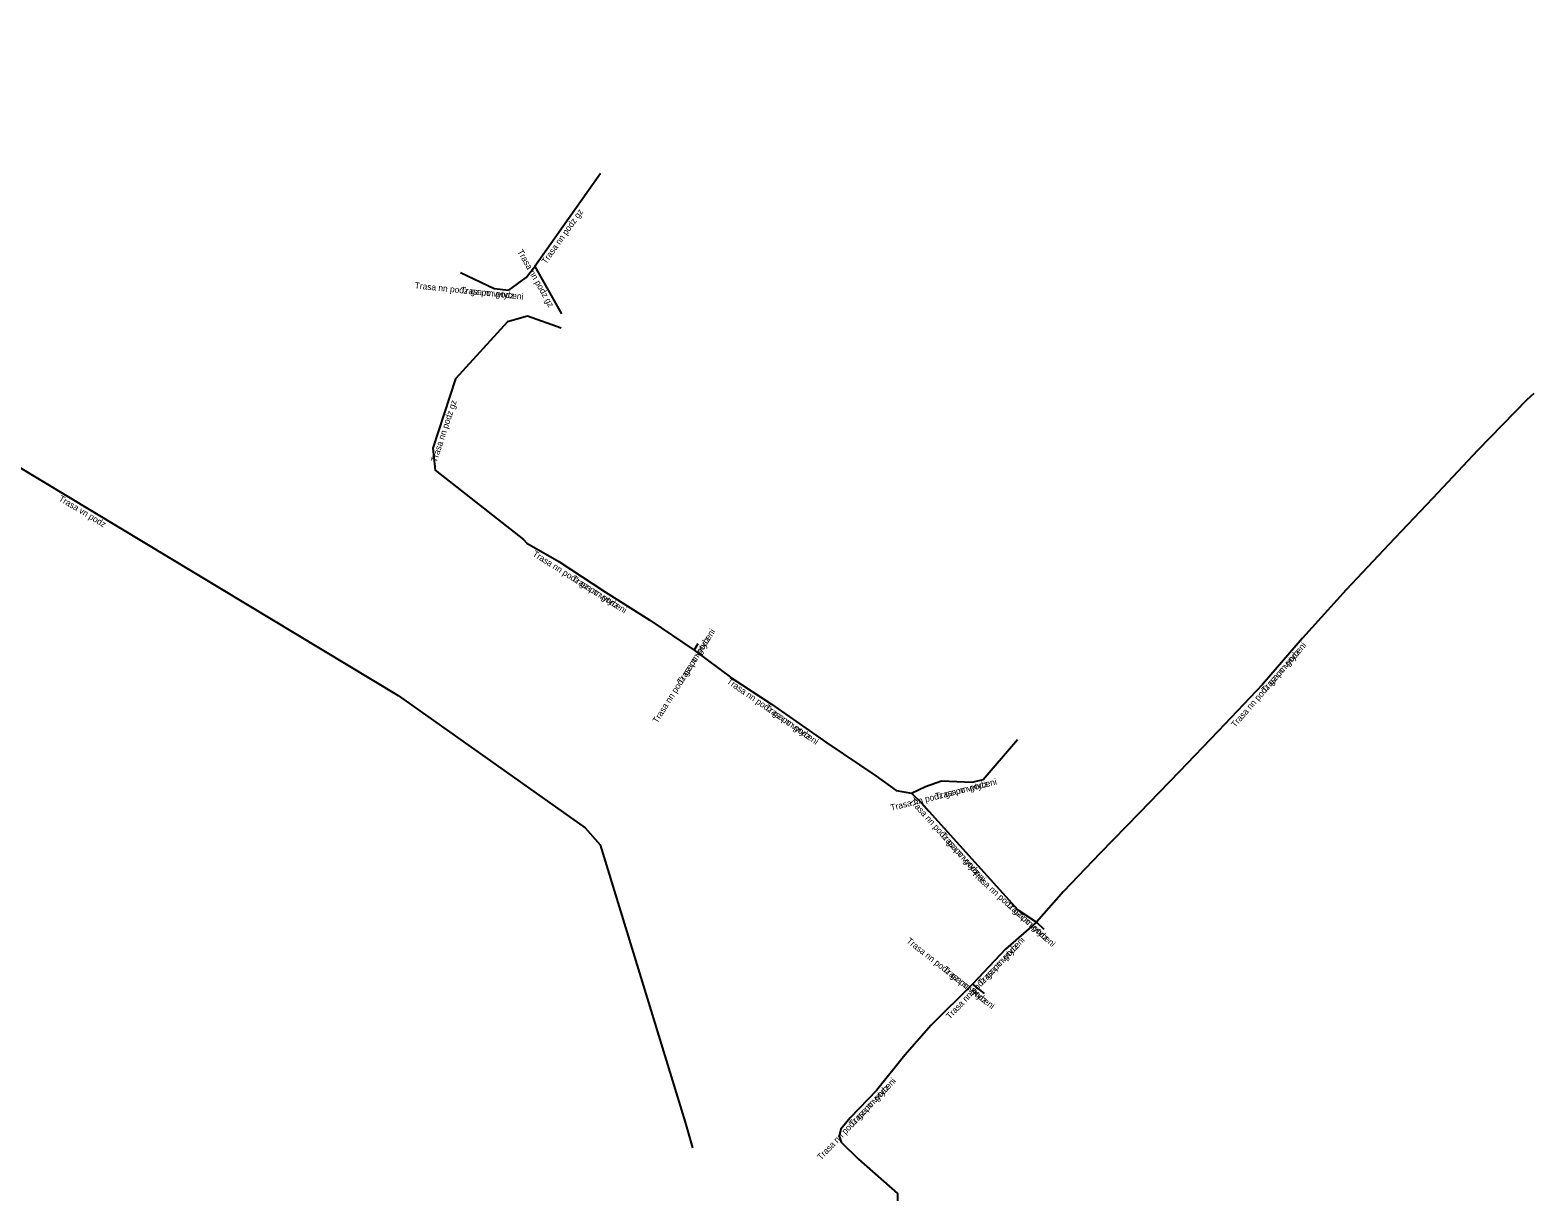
# Model space of a CAD drawing. Extents: x -747115 to -746877, y -964696 to -964505.
# Drawn here: x -746996.4 to -746876.6, y -964695.7 to -964602.4 of the extents above; entities that cross this region are included whole.
import ezdxf

# ---------------------------------------------------------------- set-up
doc = ezdxf.new("R2010")
doc.units = 0
for name, color, linetype in [('Popiskový text - Ostatní atributy Trasy', 7, 'Continuous'), ('Spojnice NN', 7, 'Continuous'), ('Spojnice VN', 7, 'Continuous')]:
    doc.layers.add(name, color=color, linetype=linetype)

msp = doc.modelspace()

# ---------------------------------------------------------------- linework, layer by layer
at = {"layer": 'Spojnice NN'}
for points in [[(-746950.98, -964613.88), (-746956.22, -964621.29)], [(-746962.14, -964621.76), (-746959.45, -964623.04), (-746958.29, -964623.16), (-746956.92, -964622.17), (-746956.22, -964621.29)], [(-746962.14, -964621.76), (-746959.45, -964623.04), (-746958.29, -964623.16), (-746956.92, -964622.17), (-746956.22, -964621.29)], [(-746956.22, -964621.29), (-746954.09, -964625.05)], [(-746954.12, -964626.2), (-746956.8, -964625.24), (-746958.4, -964625.69), (-746962.53, -964630.25), (-746964.34, -964635.75), (-746964.17, -964637.51), (-746957.13, -964643.03)], [(-746876.63, -964631.4), (-746877.2, -964631.92), (-746881.11, -964635.93), (-746884.71, -964639.78), (-746888.2, -964643.44), (-746891.58, -964647.06), (-746895.07, -964650.91), (-746898.26, -964654.58), (-746901.79, -964658.32), (-746904.89, -964661.54), (-746908.08, -964664.84), (-746911.19, -964668.04), (-746914.11, -964671.09), (-746916.27, -964673.53)], [(-746876.63, -964631.4), (-746877.2, -964631.92), (-746881.11, -964635.93), (-746884.71, -964639.78), (-746888.2, -964643.44), (-746891.58, -964647.06), (-746895.07, -964650.91), (-746898.26, -964654.58), (-746901.79, -964658.32), (-746904.89, -964661.54), (-746908.08, -964664.84), (-746911.19, -964668.04), (-746914.11, -964671.09), (-746916.27, -964673.53)], [(-746957.13, -964643.03), (-746956.85, -964643.32), (-746954.31, -964644.78), (-746950.68, -964647.18), (-746947.05, -964649.47), (-746943.54, -964651.86)], [(-746957.13, -964643.03), (-746956.85, -964643.32), (-746954.31, -964644.78), (-746950.68, -964647.18), (-746947.05, -964649.47), (-746943.54, -964651.86)], [(-746943.54, -964651.86), (-746943.2, -964651.32)], [(-746943.54, -964651.86), (-746943.2, -964651.32)], [(-746943.54, -964651.86), (-746940.53, -964654.08), (-746937.38, -964656.16), (-746932.95, -964659.24), (-746929.05, -964661.87), (-746927.43, -964663.03), (-746926.22, -964663.25)], [(-746943.54, -964651.86), (-746940.53, -964654.08), (-746937.38, -964656.16), (-746932.95, -964659.24), (-746929.05, -964661.87), (-746927.43, -964663.03), (-746926.22, -964663.25)], [(-746926.22, -964663.25), (-746925.1, -964662.72), (-746923.83, -964662.27), (-746921.39, -964662.38), (-746920.51, -964662.16), (-746917.78, -964658.97)], [(-746926.22, -964663.25), (-746925.1, -964662.72), (-746923.83, -964662.27), (-746921.39, -964662.38), (-746920.51, -964662.16), (-746917.78, -964658.97)], [(-746926.22, -964663.25), (-746925.42, -964664.01), (-746924.83, -964664.69), (-746917.74, -964672.55), (-746916.27, -964673.53)], [(-746926.22, -964663.25), (-746925.42, -964664.01), (-746924.83, -964664.69), (-746917.74, -964672.55), (-746916.27, -964673.53)], [(-746916.27, -964673.53), (-746918.72, -964675.69), (-746921.36, -964678.46)], [(-746916.27, -964673.53), (-746918.72, -964675.69), (-746921.36, -964678.46)], [(-746916.27, -964673.53), (-746915.66, -964674.08)], [(-746916.27, -964673.53), (-746915.66, -964674.08)], [(-746921.36, -964678.46), (-746924.66, -964681.73), (-746926.74, -964684.12), (-746929.01, -964686.95), (-746931.09, -964689.13), (-746931.84, -964690.03), (-746931.99, -964690.59), (-746931.81, -964691.05), (-746930.43, -964692.42), (-746927.33, -964695.16), (-746927.32, -964695.74)], [(-746921.36, -964678.46), (-746924.66, -964681.73), (-746926.74, -964684.12), (-746929.01, -964686.95), (-746931.09, -964689.13), (-746931.84, -964690.03), (-746931.99, -964690.59), (-746931.81, -964691.05), (-746930.43, -964692.42), (-746927.33, -964695.16), (-746927.32, -964695.74)], [(-746921.36, -964678.46), (-746920.42, -964679.2)], [(-746921.36, -964678.46), (-746920.42, -964679.2)]]:
    msp.add_lwpolyline(points, dxfattribs=at)
at = {"layer": 'Spojnice VN'}
msp.add_lwpolyline([(-747053.61, -964602.45), (-747034.02, -964615.16), (-746967.11, -964655.47), (-746952.2, -964666.01), (-746951.01, -964667.36), (-746944.25, -964689.46), (-746943.66, -964691.51)], dxfattribs=at)

# ---------------------------------------------------------------- texts
at = {"layer": 'Popiskový text - Ostatní atributy Trasy'}
for s, rotation, p in [('Trasa nn podz gz', 54.7332, (-746955.32, -964621.14)), ('Trasa nn podz gz', 299.57, (-746957.64, -964620.1)), ('Trasa nn podz gz po vytyceni', 354.0939, (-746965.81, -964623.03)), ('Trasa nn podz', 354.0939, (-746962.15, -964623.41)), ('Trasa nn podz gz', 71.7435, (-746964.05, -964636.93)), ('Trasa vn podz', 328.9316, (-746994.2, -964639.91)), ('Trasa nn podz gz po vytyceni', 327.7541, (-746956.45, -964644.31)), ('Trasa nn podz', 327.7541, (-746953.33, -964646.28)), ('Trasa nn podz gz po vytyceni', 57.8043, (-746946.46, -964657.72)), ('Trasa nn podz', 57.8043, (-746944.5, -964654.6)), ('Trasa nn podz gz po vytyceni', 49.0025, (-746900.43, -964658.06)), ('Trasa nn podz', 49.0025, (-746898.01, -964655.28)), ('Trasa nn podz gz po vytyceni', 325.1907, (-746940.98, -964654.45)), ('Trasa nn podz', 325.1907, (-746937.95, -964656.55)), ('Trasa nn podz gz po vytyceni', 14.0362, (-746927.82, -964664.66)), ('Trasa nn podz', 14.0362, (-746924.25, -964663.76)), ('Trasa nn podz gz po vytyceni', 312.0516, (-746926.42, -964663.89)), ('Trasa nn podz', 312.0516, (-746923.95, -964666.63)), ('Trasa nn podz gz po vytyceni', 317.9609, (-746921.47, -964669.71)), ('Trasa nn podz', 317.9609, (-746918.74, -964672.18)), ('Trasa nn podz gz po vytyceni', 321.789, (-746926.66, -964675.11)), ('Trasa nn podz gz po vytyceni', 46.3765, (-746923.16, -964681.29)), ('Trasa nn podz', 46.3765, (-746920.61, -964678.62)), ('Trasa nn podz', 321.789, (-746923.76, -964677.39)), ('Trasa nn podz gz po vytyceni', 46.3447, (-746933.42, -964692.52)), ('Trasa nn podz', 46.3447, (-746930.88, -964689.85))]:
    msp.add_text(s, height=0.5, rotation=rotation, dxfattribs=at).set_placement(p)

doc.saveas('drawing.dxf')
